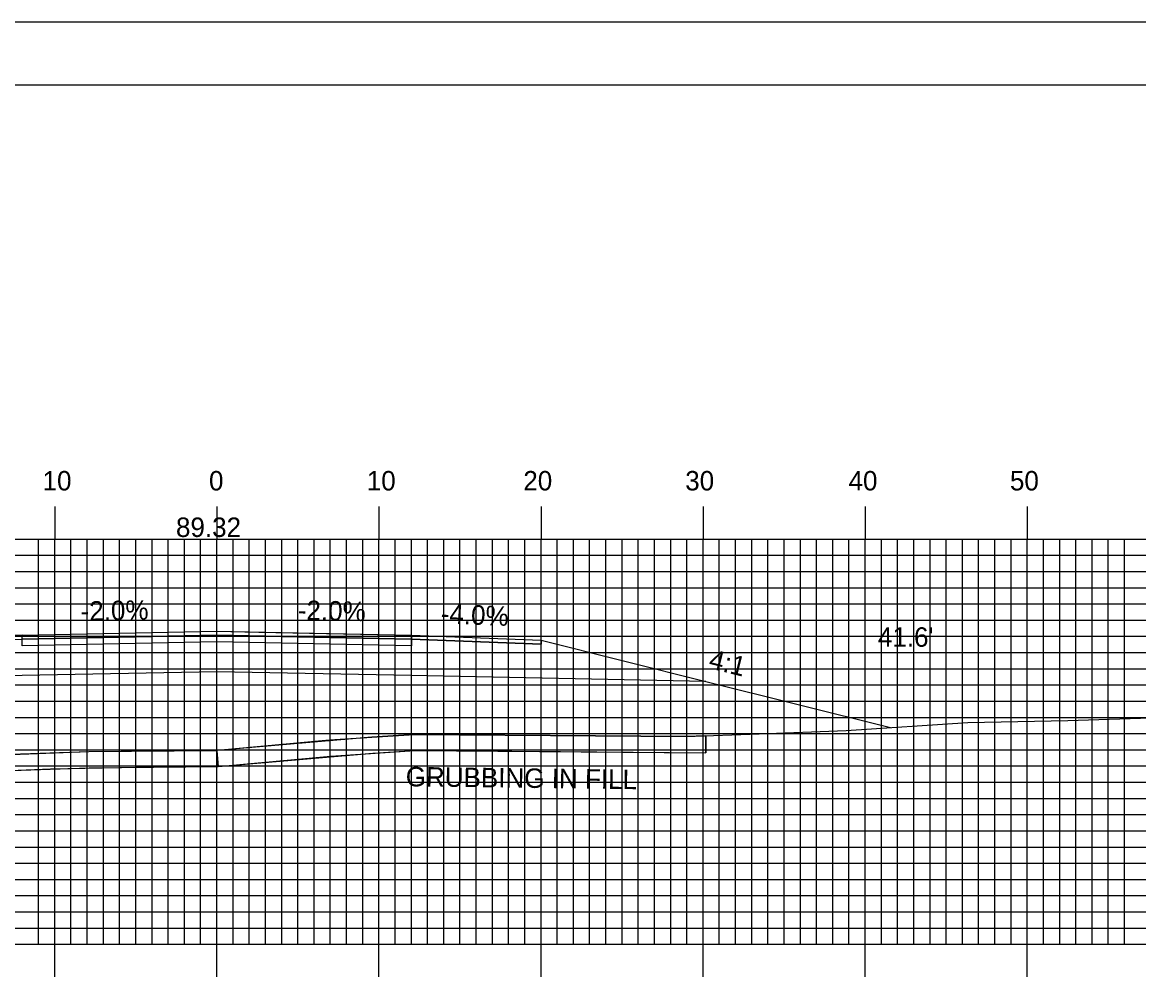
# Model space of a CAD drawing. Extents: x 1777138 to 1777481, y 442591 to 442811.
# Drawn here: x 1777291.8 to 1777360.6, y 442751.2 to 442810.5 of the extents above; entities that cross this region are included whole.
import ezdxf

# ---------------------------------------------------------------- set-up
doc = ezdxf.new("R2010")
doc.units = 0
for name, color, linetype in [('ANNOTATION', 7, 'Continuous'), ('BORDER', 7, 'Continuous'), ('D_Roadway_Centerline', 7, 'Continuous'), ('D_Roadway_Centerline_Text', 7, 'Continuous'), ('D_Roadway_Edge_Shoulder', 7, 'Continuous'), ('D_Roadway_Edge_TW', 7, 'Continuous'), ('D_Roadway_Pavement', 7, 'Continuous'), ('D_Roadway_SlopeLines', 7, 'Continuous'), ('D_Roadway_SubGrade', 7, 'Continuous'), ('D_Text_Standard', 7, 'Continuous'), ('GRUBBING IN FILL', 7, 'Continuous'), ('H_V ANNOTATION', 7, 'Continuous'), ('MAJOR', 7, 'Continuous'), ('MINOR', 7, 'Continuous'), ('PLOT BOUNDARY', 7, 'Continuous'), ('S_Roadway_Centerline', 7, 'Continuous')]:
    doc.layers.add(name, color=color, linetype=linetype)

msp = doc.modelspace()

# ---------------------------------------------------------------- linework, layer by layer
at = {"layer": 'BORDER'}
msp.add_lwpolyline([(1777154.164, 442596.665), (1777474.164, 442596.665), (1777474.164, 442806.665), (1777154.164, 442806.665)], close=True, dxfattribs=at)
at = {"layer": 'D_Roadway_Centerline'}
msp.add_lwpolyline([(1777247.093, 442763.945), (1777262.404, 442769.048), (1777262.905, 442769.173), (1777265.042, 442769.708), (1777265.044, 442769.708), (1777274.398, 442772.047), (1777274.405, 442772.048), (1777291.75, 442772.743), (1777291.764, 442772.743), (1777303.761, 442772.983), (1777303.763, 442772.983), (1777306.365, 442772.931), (1777315.76, 442772.743), (1777315.764, 442772.743), (1777315.767, 442772.743), (1777323.764, 442772.423), (1777323.767, 442772.422), (1777333.937, 442769.879), (1777345.318, 442767.034), (1777345.321, 442767.033)], dxfattribs=at)
at = {"layer": 'D_Roadway_Edge_Shoulder'}
for points in [[(1777291.764, 442772.743), (1777274.405, 442772.048), (1777274.405, 442771.798), (1777291.764, 442772.493)], [(1777315.764, 442772.743), (1777323.764, 442772.423), (1777323.764, 442772.173), (1777315.764, 442772.493)]]:
    msp.add_lwpolyline(points, close=True, dxfattribs=at)
at = {"layer": 'D_Roadway_Edge_TW'}
msp.add_lwpolyline([(1777291.764, 442772.493), (1777291.764, 442772.743), (1777303.763, 442772.983), (1777315.764, 442772.743), (1777315.764, 442772.493), (1777303.763, 442772.733)], close=True, dxfattribs=at)
at = {"layer": 'D_Roadway_Pavement'}
msp.add_lwpolyline([(1777291.764, 442772.076), (1777291.764, 442772.493), (1777303.763, 442772.733), (1777315.764, 442772.493), (1777315.764, 442772.076), (1777303.763, 442772.316)], close=True, dxfattribs=at)
at = {"layer": 'D_Roadway_SlopeLines'}
msp.add_lwpolyline([(1777323.764, 442772.423), (1777333.937, 442769.879), (1777345.321, 442767.033)], dxfattribs=at)
at = {"layer": 'D_Roadway_SubGrade'}
msp.add_lwpolyline([(1777291.764, 442770.243), (1777265.044, 442769.708), (1777274.405, 442772.048), (1777274.405, 442771.798), (1777291.764, 442772.493), (1777303.763, 442772.733), (1777315.764, 442772.493), (1777323.764, 442772.173), (1777323.764, 442772.423), (1777333.937, 442769.879), (1777315.764, 442770.243), (1777303.763, 442770.483)], close=True, dxfattribs=at)
at = {"layer": 'GRUBBING IN FILL'}
msp.add_line((1777333.937, 442766.533), (1777333.937, 442765.484), dxfattribs=at)
msp.add_line((1777333.937, 442766.533), (1777333.937, 442765.484), dxfattribs=at)
for points in [[(1777303.85, 442764.633), (1777313.386, 442765.448), (1777315.982, 442765.616), (1777324.959, 442765.55), (1777333.937, 442765.484), (1777333.937, 442766.533), (1777332.71, 442766.493), (1777324.331, 442766.555), (1777315.953, 442766.617), (1777313.332, 442766.447), (1777303.764, 442765.63)], [(1777303.85, 442764.633), (1777313.386, 442765.448), (1777315.982, 442765.616), (1777324.959, 442765.55), (1777333.937, 442765.484), (1777333.937, 442766.533), (1777332.71, 442766.493), (1777324.331, 442766.555), (1777315.953, 442766.617), (1777313.332, 442766.447), (1777303.764, 442765.63)], [(1777265.044, 442764.541), (1777272.776, 442764.725), (1777279.815, 442764.949), (1777288.951, 442765.284), (1777295.875, 442765.555), (1777303.764, 442765.63), (1777303.764, 442764.633), (1777299.873, 442764.594), (1777293.494, 442764.476), (1777288.994, 442764.285), (1777279.85, 442763.95), (1777268.924, 442763.635), (1777265.044, 442763.544)], [(1777265.044, 442764.541), (1777272.776, 442764.725), (1777279.815, 442764.949), (1777288.951, 442765.284), (1777295.875, 442765.555), (1777303.764, 442765.63), (1777303.764, 442764.633), (1777299.873, 442764.594), (1777293.494, 442764.476), (1777288.994, 442764.285), (1777279.85, 442763.95), (1777268.924, 442763.635), (1777265.044, 442763.544)]]:
    msp.add_lwpolyline(points, close=True, dxfattribs=at)
msp.add_lwpolyline([(1777265.044, 442763.544), (1777272.804, 442763.725), (1777286.895, 442764.174), (1777291.092, 442764.396), (1777295.897, 442764.555), (1777303.85, 442764.633), (1777310.79, 442765.28), (1777315.982, 442765.616), (1777333.937, 442765.484)], dxfattribs=at)
msp.add_lwpolyline([(1777265.044, 442763.544), (1777272.804, 442763.725), (1777286.895, 442764.174), (1777291.092, 442764.396), (1777295.897, 442764.555), (1777303.85, 442764.633), (1777310.79, 442765.28), (1777315.982, 442765.616), (1777333.937, 442765.484)], dxfattribs=at)
at = {"layer": 'MAJOR'}
for p, q in [((1777293.764, 442780.669), (1777293.764, 442778.665)), ((1777303.764, 442780.669), (1777303.764, 442778.665)), ((1777313.764, 442780.669), (1777313.764, 442778.665)), ((1777323.764, 442780.669), (1777323.764, 442778.665)), ((1777333.764, 442780.669), (1777333.764, 442778.665)), ((1777343.764, 442780.669), (1777343.764, 442778.665)), ((1777353.764, 442780.669), (1777353.764, 442778.665)), ((1777163.764, 442778.665), (1777443.764, 442778.665)), ((1777163.764, 442778.665), (1777443.764, 442778.665)), ((1777293.764, 442753.665), (1777293.764, 442778.665)), ((1777303.764, 442753.665), (1777303.764, 442778.665)), ((1777313.764, 442753.665), (1777313.764, 442778.665)), ((1777323.764, 442753.665), (1777323.764, 442778.665)), ((1777333.764, 442753.665), (1777333.764, 442778.665)), ((1777343.764, 442753.665), (1777343.764, 442778.665)), ((1777353.764, 442753.665), (1777353.764, 442778.665)), ((1777163.764, 442773.665), (1777443.764, 442773.665)), ((1777163.764, 442768.665), (1777443.764, 442768.665)), ((1777163.764, 442763.665), (1777443.764, 442763.665)), ((1777163.764, 442758.665), (1777443.764, 442758.665)), ((1777163.764, 442753.665), (1777443.764, 442753.665)), ((1777163.764, 442753.665), (1777443.764, 442753.665)), ((1777293.764, 442751.661), (1777293.764, 442753.665)), ((1777303.764, 442751.661), (1777303.764, 442753.665)), ((1777313.764, 442751.661), (1777313.764, 442753.665)), ((1777323.764, 442751.661), (1777323.764, 442753.665)), ((1777333.764, 442751.661), (1777333.764, 442753.665)), ((1777343.764, 442751.661), (1777343.764, 442753.665)), ((1777353.764, 442751.661), (1777353.764, 442753.665))]:
    msp.add_line(p, q, dxfattribs=at)
at = {"layer": 'MINOR'}
for p, q in [((1777292.764, 442753.665), (1777292.764, 442778.665)), ((1777294.764, 442753.665), (1777294.764, 442778.665)), ((1777295.764, 442753.665), (1777295.764, 442778.665)), ((1777296.764, 442753.665), (1777296.764, 442778.665)), ((1777297.764, 442753.665), (1777297.764, 442778.665)), ((1777298.764, 442753.665), (1777298.764, 442778.665)), ((1777299.764, 442753.665), (1777299.764, 442778.665)), ((1777300.764, 442753.665), (1777300.764, 442778.665)), ((1777301.764, 442753.665), (1777301.764, 442778.665)), ((1777302.764, 442753.665), (1777302.764, 442778.665)), ((1777304.764, 442753.665), (1777304.764, 442778.665)), ((1777305.764, 442753.665), (1777305.764, 442778.665)), ((1777306.764, 442753.665), (1777306.764, 442778.665)), ((1777307.764, 442753.665), (1777307.764, 442778.665)), ((1777308.764, 442753.665), (1777308.764, 442778.665)), ((1777309.764, 442753.665), (1777309.764, 442778.665)), ((1777310.764, 442753.665), (1777310.764, 442778.665)), ((1777311.764, 442753.665), (1777311.764, 442778.665)), ((1777312.764, 442753.665), (1777312.764, 442778.665)), ((1777314.764, 442753.665), (1777314.764, 442778.665)), ((1777315.764, 442753.665), (1777315.764, 442778.665)), ((1777316.764, 442753.665), (1777316.764, 442778.665)), ((1777317.764, 442753.665), (1777317.764, 442778.665)), ((1777318.764, 442753.665), (1777318.764, 442778.665)), ((1777319.764, 442753.665), (1777319.764, 442778.665)), ((1777320.764, 442753.665), (1777320.764, 442778.665)), ((1777321.764, 442753.665), (1777321.764, 442778.665)), ((1777322.764, 442753.665), (1777322.764, 442778.665)), ((1777324.764, 442753.665), (1777324.764, 442778.665)), ((1777325.764, 442753.665), (1777325.764, 442778.665)), ((1777326.764, 442753.665), (1777326.764, 442778.665)), ((1777327.764, 442753.665), (1777327.764, 442778.665)), ((1777328.764, 442753.665), (1777328.764, 442778.665)), ((1777329.764, 442753.665), (1777329.764, 442778.665)), ((1777330.764, 442753.665), (1777330.764, 442778.665)), ((1777331.764, 442753.665), (1777331.764, 442778.665)), ((1777332.764, 442753.665), (1777332.764, 442778.665)), ((1777334.764, 442753.665), (1777334.764, 442778.665)), ((1777335.764, 442753.665), (1777335.764, 442778.665)), ((1777336.764, 442753.665), (1777336.764, 442778.665)), ((1777337.764, 442753.665), (1777337.764, 442778.665)), ((1777338.764, 442753.665), (1777338.764, 442778.665)), ((1777339.764, 442753.665), (1777339.764, 442778.665)), ((1777340.764, 442753.665), (1777340.764, 442778.665)), ((1777341.764, 442753.665), (1777341.764, 442778.665)), ((1777342.764, 442753.665), (1777342.764, 442778.665)), ((1777344.764, 442753.665), (1777344.764, 442778.665)), ((1777345.764, 442753.665), (1777345.764, 442778.665)), ((1777346.764, 442753.665), (1777346.764, 442778.665)), ((1777347.764, 442753.665), (1777347.764, 442778.665)), ((1777348.764, 442753.665), (1777348.764, 442778.665)), ((1777349.764, 442753.665), (1777349.764, 442778.665)), ((1777350.764, 442753.665), (1777350.764, 442778.665)), ((1777351.764, 442753.665), (1777351.764, 442778.665)), ((1777352.764, 442753.665), (1777352.764, 442778.665)), ((1777354.764, 442753.665), (1777354.764, 442778.665)), ((1777355.764, 442753.665), (1777355.764, 442778.665)), ((1777356.764, 442753.665), (1777356.764, 442778.665)), ((1777357.764, 442753.665), (1777357.764, 442778.665)), ((1777358.764, 442753.665), (1777358.764, 442778.665)), ((1777359.764, 442753.665), (1777359.764, 442778.665)), ((1777163.764, 442777.665), (1777443.764, 442777.665)), ((1777163.764, 442776.665), (1777443.764, 442776.665)), ((1777163.764, 442775.665), (1777443.764, 442775.665)), ((1777163.764, 442774.665), (1777443.764, 442774.665)), ((1777163.764, 442772.665), (1777443.764, 442772.665)), ((1777163.764, 442771.665), (1777443.764, 442771.665)), ((1777163.764, 442770.665), (1777443.764, 442770.665)), ((1777163.764, 442769.665), (1777443.764, 442769.665)), ((1777163.764, 442767.665), (1777443.764, 442767.665)), ((1777163.764, 442766.665), (1777443.764, 442766.665)), ((1777163.764, 442765.665), (1777443.764, 442765.665)), ((1777163.764, 442764.665), (1777443.764, 442764.665)), ((1777163.764, 442762.665), (1777443.764, 442762.665)), ((1777163.764, 442761.665), (1777443.764, 442761.665)), ((1777163.764, 442760.665), (1777443.764, 442760.665)), ((1777163.764, 442759.665), (1777443.764, 442759.665)), ((1777163.764, 442757.665), (1777443.764, 442757.665)), ((1777163.764, 442756.665), (1777443.764, 442756.665)), ((1777163.764, 442755.665), (1777443.764, 442755.665)), ((1777163.764, 442754.665), (1777443.764, 442754.665))]:
    msp.add_line(p, q, dxfattribs=at)
at = {"layer": 'PLOT BOUNDARY'}
msp.add_lwpolyline([(1777137.977, 442590.547), (1777477.977, 442590.547), (1777477.977, 442810.547), (1777137.977, 442810.547)], close=True, dxfattribs=at)
at = {"layer": 'S_Roadway_Centerline'}
msp.add_lwpolyline([(1777233.05, 442763.188), (1777242.805, 442763.824), (1777247.917, 442763.968), (1777265.37, 442764.552), (1777272.776, 442764.725), (1777286.853, 442765.173), (1777291.049, 442765.395), (1777295.875, 442765.555), (1777303.799, 442765.633), (1777310.712, 442766.277), (1777315.953, 442766.617), (1777332.71, 442766.493), (1777337.225, 442766.642), (1777342.583, 442766.859), (1777350.098, 442767.338), (1777356.271, 442767.473), (1777367.154, 442767.831)], dxfattribs=at)

# ---------------------------------------------------------------- texts
at = {"layer": 'ANNOTATION'}
for s, rotation, p in [('-2.0%', 1.14582, (1777295.369, 442773.616)), ('-2.0%', 358.85432, (1777308.748, 442773.684)), ('-4.0%', 357.70946, (1777317.557, 442773.473)), ('4:1', 345.96195, (1777334.049, 442770.713))]:
    msp.add_text(s, height=1.2, rotation=rotation, dxfattribs=at).set_placement(p)
at = {"layer": 'D_Roadway_Centerline'}
for s, p in [('C', (1777303.758, 442772.983)), ('L', (1777303.763, 442772.976))]:
    msp.add_text(s, height=0.0146, dxfattribs=at).set_placement(p)
at = {"layer": 'D_Roadway_Centerline_Text'}
msp.add_text('89.32', height=1.2, dxfattribs=at).set_placement((1777301.243, 442778.795))
at = {"layer": 'D_Text_Standard'}
msp.add_text("41.6'", height=1.2, dxfattribs=at).set_placement((1777344.547, 442772.021))
at = {"layer": 'GRUBBING IN FILL'}
msp.add_text('GRUBBING IN FILL', height=1.2, rotation=359.26556, dxfattribs=at).set_placement((1777315.414, 442763.414))
at = {"layer": 'H_V ANNOTATION'}
for s, p in [('10', (1777293.014, 442781.665)), ('0', (1777303.282, 442781.665)), ('10', (1777313.014, 442781.665)), ('20', (1777322.672, 442781.665)), ('30', (1777332.661, 442781.665)), ('40', (1777342.736, 442781.665)), ('50', (1777352.693, 442781.665))]:
    msp.add_text(s, height=1.2, dxfattribs=at).set_placement(p)

doc.saveas('drawing.dxf')
